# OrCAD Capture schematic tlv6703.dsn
size A
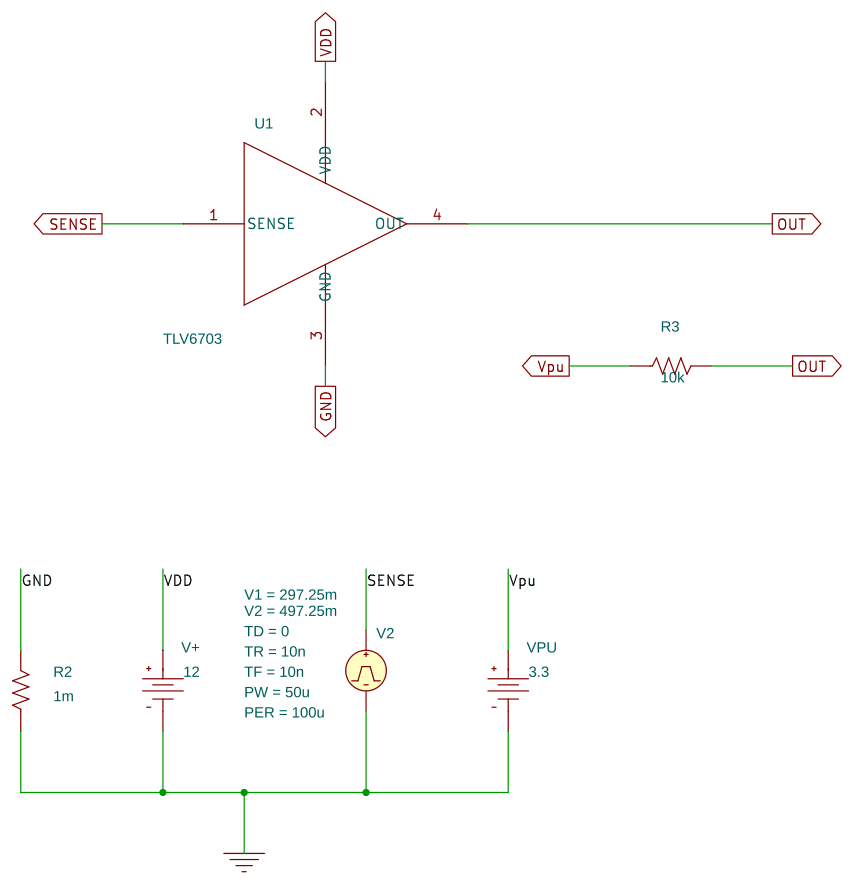
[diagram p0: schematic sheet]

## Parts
R2  1m  [AXRC05]
R3  10k  [AXRC05]
U1  TLV6703
V2  VPULSE
V+  VDC
VPU  VDC

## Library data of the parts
R2 R3 = R
U1 = TLV6703
V2 = VPULSE: PER: 100u; PW: 50u; TD: 0; TF: 10n; TR: 10n; V1: 297.25m; V2: 497.25m
V+ = VDC: DC: 12
VPU = VDC: DC: 3.3

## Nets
GND: R2.2 U1.3(GND)
VDD: U1.2(VDD) V+.0(+)
0: R2.1 V2.2(-) V+.1(-) VPU.1(-)
OUT: R3.2 U1.4(OUT)
SENSE: U1.1(SENSE) V2.1(+)
Vpu: R3.1 VPU.0(+)
